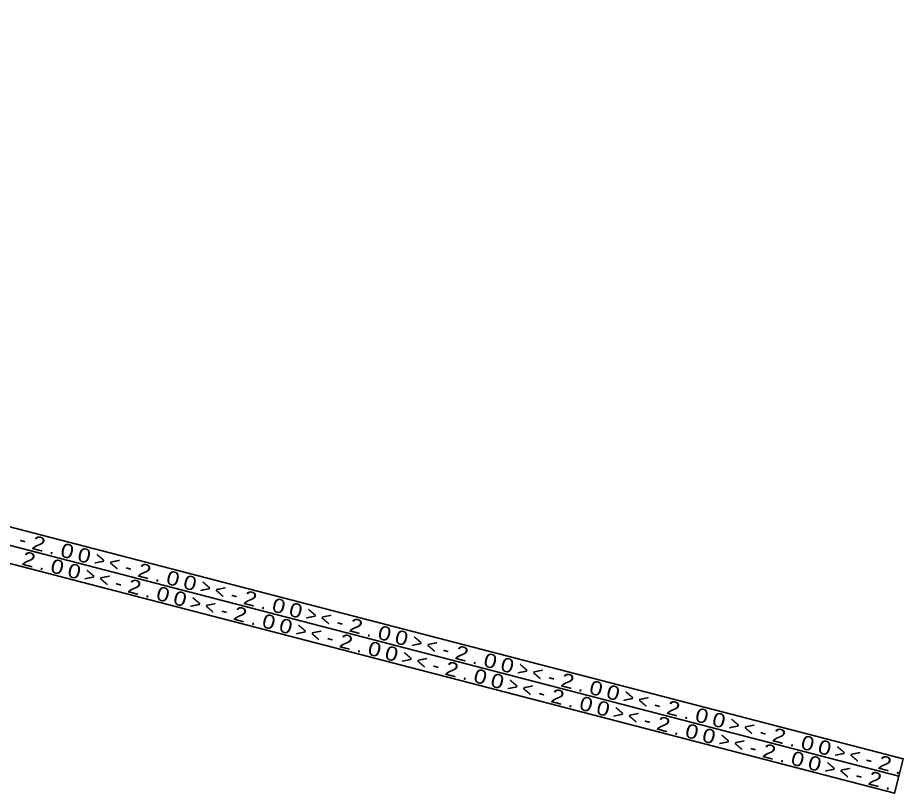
# Model space of a CAD drawing. Extents: x 49942 to 56479, y 47140 to 53283.
# Drawn here: x 55882 to 56479, y 49210 to 49733 of the extents above; entities that cross this region are included whole.
import ezdxf
from ezdxf.enums import TextEntityAlignment as Align

# ---------------------------------------------------------------- set-up
doc = ezdxf.new("R2010")
doc.units = 0
doc.header["$LTSCALE"] = 2
doc.layers.add('63', color=7, linetype='Continuous', lineweight=35)

msp = doc.modelspace()

# ---------------------------------------------------------------- linework, layer by layer
at = {"layer": '63'}
for points in [[(54503.671, 49720.911), (56472.661, 49209.506), (56475.677, 49221.12), (54506.687, 49732.526)], [(54656.01, 49706.141), (56478.694, 49232.735), (56475.677, 49221.12), (54652.993, 49694.526)]]:
    msp.add_lwpolyline(points, close=True, dxfattribs=at)

# ---------------------------------------------------------------- texts
for s, width, p in [('2', 1.2, (55894.745, 49373.246)), ('-', 1.1, (55884.151, 49375.997)), ('0', 1.2, (55913.95, 49368.257)), ('2', 1.2, (55888.029, 49362.592)), ('0', 1.2, (55925.412, 49365.28)), ('>', 0.95, (55936.005, 49362.529)), ('0', 1.2, (55907.235, 49357.604)), ('0', 1.2, (55918.697, 49354.626)), ('<', 0.95, (55945.73, 49360.003)), ('2', 1.2, (55966.048, 49354.726)), ('>', 0.95, (55929.29, 49351.875)), ('-', 1.1, (55955.455, 49357.477)), ('0', 1.2, (55985.253, 49349.738)), ('<', 0.95, (55939.015, 49349.349)), ('2', 1.2, (55959.333, 49344.072)), ('0', 1.2, (55996.716, 49346.761)), ('>', 0.95, (56007.309, 49344.009)), ('-', 1.1, (55948.739, 49346.824)), ('0', 1.2, (55978.538, 49339.084)), ('0', 1.2, (55990, 49336.107)), ('<', 0.95, (56017.034, 49341.484)), ('2', 1.2, (56037.352, 49336.206)), ('>', 0.95, (56000.594, 49333.355)), ('-', 1.1, (56026.758, 49338.958)), ('0', 1.2, (56056.557, 49331.218)), ('<', 0.95, (56010.318, 49330.83)), ('2', 1.2, (56030.636, 49325.552)), ('0', 1.2, (56068.019, 49328.241)), ('>', 0.95, (56078.612, 49325.49)), ('-', 1.1, (56020.043, 49328.304)), ('0', 1.2, (56049.841, 49320.564)), ('<', 0.95, (56088.337, 49322.964)), ('0', 1.2, (56061.304, 49317.587)), ('>', 0.95, (56071.897, 49314.836)), ('-', 1.1, (56098.062, 49320.438)), ('2', 1.2, (56108.655, 49317.687)), ('0', 1.2, (56127.86, 49312.699)), ('<', 0.95, (56081.622, 49312.31)), ('2', 1.2, (56101.94, 49307.033)), ('0', 1.2, (56139.323, 49309.721)), ('>', 0.95, (56149.916, 49306.97)), ('-', 1.1, (56091.346, 49309.784)), ('0', 1.2, (56121.145, 49302.045)), ('<', 0.95, (56159.641, 49304.444)), ('0', 1.2, (56132.607, 49299.067)), ('>', 0.95, (56143.201, 49296.316)), ('-', 1.1, (56169.365, 49301.918)), ('2', 1.2, (56179.959, 49299.167)), ('0', 1.2, (56199.164, 49294.179)), ('<', 0.95, (56152.925, 49293.79)), ('2', 1.2, (56173.243, 49288.513)), ('0', 1.2, (56210.626, 49291.202)), ('-', 1.1, (56162.65, 49291.265)), ('0', 1.2, (56192.448, 49283.525)), ('>', 0.95, (56221.219, 49288.45)), ('<', 0.95, (56230.944, 49285.925)), ('0', 1.2, (56203.911, 49280.548)), ('>', 0.95, (56214.504, 49277.797)), ('-', 1.1, (56240.669, 49283.399)), ('2', 1.2, (56251.262, 49280.647)), ('<', 0.95, (56224.229, 49275.271)), ('2', 1.2, (56244.547, 49269.993)), ('0', 1.2, (56270.467, 49275.659)), ('0', 1.2, (56281.93, 49272.682)), ('-', 1.1, (56233.953, 49272.745)), ('0', 1.2, (56263.752, 49265.005)), ('>', 0.95, (56292.523, 49269.931)), ('<', 0.95, (56302.248, 49267.405)), ('0', 1.2, (56275.214, 49262.028)), ('>', 0.95, (56285.808, 49259.277)), ('-', 1.1, (56311.972, 49264.879)), ('2', 1.2, (56322.565, 49262.128)), ('<', 0.95, (56295.532, 49256.751)), ('0', 1.2, (56341.771, 49257.14)), ('0', 1.2, (56353.233, 49254.162)), ('-', 1.1, (56305.257, 49254.225)), ('2', 1.2, (56315.85, 49251.474)), ('0', 1.2, (56335.055, 49246.486)), ('>', 0.95, (56363.826, 49251.411)), ('<', 0.95, (56373.551, 49248.885)), ('0', 1.2, (56346.518, 49243.509)), ('-', 1.1, (56383.276, 49246.36)), ('2', 1.2, (56393.869, 49243.608)), ('>', 0.95, (56357.111, 49240.757)), ('<', 0.95, (56366.836, 49238.231)), ('0', 1.2, (56413.074, 49238.62)), ('0', 1.2, (56424.536, 49235.643)), ('-', 1.1, (56376.56, 49235.706)), ('2', 1.2, (56387.154, 49232.954)), ('>', 0.95, (56435.13, 49232.891)), ('0', 1.2, (56406.359, 49227.966)), ('0', 1.2, (56417.821, 49224.989)), ('<', 0.95, (56444.854, 49230.366)), ('-', 1.1, (56454.579, 49227.84)), ('2', 1.2, (56465.172, 49225.088)), ('>', 0.95, (56428.415, 49222.238)), ('<', 0.95, (56438.139, 49219.712)), ('-', 1.1, (56447.864, 49217.186)), ('2', 1.2, (56458.457, 49214.434))]:
    msp.add_text(s, height=9.6, rotation=345.44, dxfattribs=dict(at, width=width)).set_placement(p, align=Align.CENTER)
for p in [(55904.347, 49370.752), (55897.632, 49360.098), (55975.651, 49352.232), (55968.935, 49341.578), (56046.954, 49333.712), (56040.239, 49323.058), (56118.258, 49315.193), (56111.542, 49304.539), (56189.561, 49296.673), (56182.846, 49286.019), (56260.865, 49278.153), (56254.149, 49267.499), (56332.168, 49259.634), (56325.453, 49248.98), (56403.472, 49241.114), (56396.756, 49230.46), (56474.775, 49222.594), (56468.06, 49211.94)]:
    msp.add_text('.', height=9.6, rotation=345.44, dxfattribs=at).set_placement(p, align=Align.CENTER)

doc.saveas('drawing.dxf')
